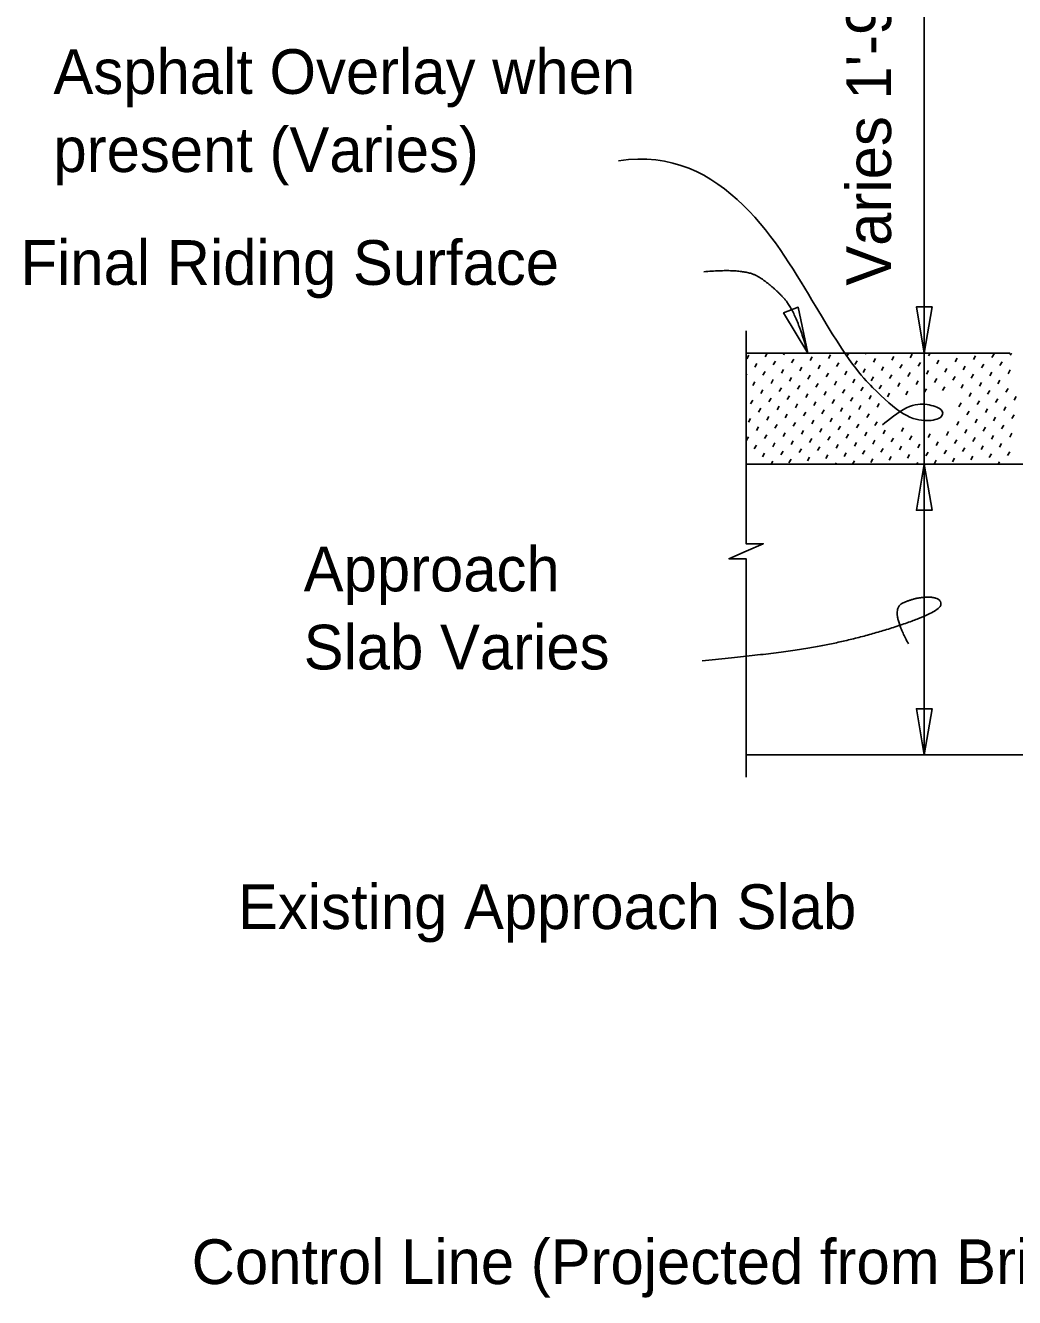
# Model space of a CAD drawing. Extents: x 21652.5 to 21723.2, y 56079.2 to 56117.9.
# Drawn here: x 21676.35 to 21680.81, y 56098.69 to 56104.42 of the extents above; entities that cross this region are included whole.
import ezdxf

# ---------------------------------------------------------------- set-up
doc = ezdxf.new("R2010")
doc.units = 0
for name, color, linetype in [('Dimension', 7, 'Continuous'), ('ExistSuperStruct', 7, 'Continuous'), ('Miscellaneous', 7, 'Continuous'), ('TextStructures', 7, 'Continuous')]:
    doc.layers.add(name, color=color, linetype=linetype)

msp = doc.modelspace()

# ---------------------------------------------------------------- linework, layer by layer
at = {"layer": 'Dimension'}
msp.add_line((21680.4032, 56108.278), (21680.4032, 56101.1329), dxfattribs=at)
for points in [[(21679.8776, 56102.9445), (21679.8349, 56103.1514), (21679.7692, 56103.1258)], [(21680.4032, 56102.9447), (21680.4385, 56103.1529), (21680.3679, 56103.1529)], [(21680.4032, 56102.4447), (21680.4385, 56102.2364), (21680.3679, 56102.2364)], [(21680.4032, 56101.1329), (21680.4385, 56101.3412), (21680.3679, 56101.3412)]]:
    msp.add_lwpolyline(points, close=True, dxfattribs=at)
msp.add_lwpolyline([(21679.5999, 56103.0446), (21679.5999, 56102.0849), (21679.6774, 56102.0849), (21679.5999, 56102.0511), (21679.5224, 56102.0174), (21679.5999, 56102.0174), (21679.5999, 56101.0329)], dxfattribs=at)
for points, degree in [([(21679.0254, 56103.8118), (21679.4979, 56103.8867), (21680.0133, 56102.9542), (21680.1732, 56102.7831), (21680.3149, 56102.6526), (21680.4198, 56102.6342), (21680.4892, 56102.6527), (21680.4892, 56102.6938), (21680.4184, 56102.7165), (21680.3319, 56102.7165), (21680.2412, 56102.6427), (21680.2143, 56102.6214)], 3), ([(21679.4099, 56103.3113), (21679.5913, 56103.3283), (21679.716, 56103.2517), (21679.8266, 56103.1297), (21679.8776, 56102.9445)], 2), ([(21679.402, 56101.5578), (21679.7617, 56101.5913), (21680.1276, 56101.6615), (21680.4782, 56101.7804), (21680.4782, 56101.8444), (21680.3624, 56101.8444), (21680.2465, 56101.7895), (21680.3319, 56101.634)], 2)]:
    msp.add_open_spline(points, degree=degree, dxfattribs=at)
at = {"layer": 'ExistSuperStruct'}
for p, q in [((21683.8894, 56102.4446), (21679.5999, 56102.4446)), ((21679.5999, 56101.1329), (21685.053, 56101.1329))]:
    msp.add_line(p, q, dxfattribs=at)
at = {"layer": 'Miscellaneous'}
for p, q in [((21680.789, 56102.9446), (21679.5999, 56102.9446)), ((21679.6027, 56102.9182), (21679.6124, 56102.935)), ((21679.6856, 56102.9279), (21679.6953, 56102.9446)), ((21679.7686, 56102.9376), (21679.7726, 56102.9446)), ((21679.8052, 56102.901), (21679.8149, 56102.9178)), ((21679.8881, 56102.9107), (21679.8978, 56102.9275)), ((21679.9711, 56102.9204), (21679.9808, 56102.9372)), ((21680.054, 56102.9302), (21680.0624, 56102.9446)), ((21680.0906, 56102.8936), (21680.1003, 56102.9104)), ((21680.1369, 56102.9399), (21680.1397, 56102.9446)), ((21680.1735, 56102.9033), (21680.1833, 56102.9201)), ((21680.2565, 56102.913), (21680.2662, 56102.9298)), ((21680.3394, 56102.9227), (21680.3491, 56102.9395)), ((21680.4224, 56102.9324), (21680.4294, 56102.9446)), ((21680.459, 56102.8958), (21680.4687, 56102.9126)), ((21680.5053, 56102.9422), (21680.5067, 56102.9446)), ((21680.5419, 56102.9056), (21680.5516, 56102.9224)), ((21680.6248, 56102.9153), (21680.6346, 56102.9321)), ((21680.7078, 56102.925), (21680.7175, 56102.9418)), ((21680.7907, 56102.9347), (21680.7964, 56102.9446)), ((21679.5999, 56102.8472), (21679.6027, 56102.852)), ((21679.6393, 56102.8816), (21679.649, 56102.8983)), ((21679.6759, 56102.8449), (21679.6856, 56102.8617)), ((21679.7222, 56102.8913), (21679.732, 56102.9081)), ((21679.7589, 56102.8547), (21679.7686, 56102.8715)), ((21679.8418, 56102.8644), (21679.8515, 56102.8812)), ((21679.9247, 56102.8741), (21679.9344, 56102.8909)), ((21679.9613, 56102.8375), (21679.9711, 56102.8543)), ((21680.0077, 56102.8838), (21680.0174, 56102.9006)), ((21680.0443, 56102.8472), (21680.054, 56102.864)), ((21680.1272, 56102.8569), (21680.1369, 56102.8737)), ((21680.2101, 56102.8667), (21680.2199, 56102.8835)), ((21680.2931, 56102.8764), (21680.3028, 56102.8932)), ((21680.3297, 56102.8398), (21680.3394, 56102.8566)), ((21680.376, 56102.8861), (21680.3857, 56102.9029)), ((21680.4126, 56102.8495), (21680.4224, 56102.8663)), ((21680.4956, 56102.8592), (21680.5053, 56102.876)), ((21680.5785, 56102.869), (21680.5882, 56102.8857)), ((21680.6614, 56102.8787), (21680.6712, 56102.8955)), ((21680.6981, 56102.8421), (21680.7078, 56102.8589)), ((21680.7444, 56102.8884), (21680.7541, 56102.9052)), ((21680.781, 56102.8518), (21680.7907, 56102.8686)), ((21679.6296, 56102.7986), (21679.6393, 56102.8154)), ((21679.7125, 56102.8083), (21679.7222, 56102.8251)), ((21679.7955, 56102.8181), (21679.8052, 56102.8349)), ((21679.8321, 56102.7815), (21679.8418, 56102.7982)), ((21679.8784, 56102.8278), (21679.8881, 56102.8446)), ((21679.915, 56102.7912), (21679.9247, 56102.808)), ((21679.9979, 56102.8009), (21680.0077, 56102.8177)), ((21680.0809, 56102.8106), (21680.0906, 56102.8274)), ((21680.1638, 56102.8203), (21680.1735, 56102.8371)), ((21680.2004, 56102.7837), (21680.2101, 56102.8005)), ((21680.2468, 56102.8301), (21680.2565, 56102.8469)), ((21680.2834, 56102.7935), (21680.2931, 56102.8103)), ((21680.3663, 56102.8032), (21680.376, 56102.82)), ((21680.4492, 56102.8129), (21680.459, 56102.8297)), ((21680.5322, 56102.8226), (21680.5419, 56102.8394)), ((21680.5688, 56102.786), (21680.5785, 56102.8028)), ((21680.6151, 56102.8323), (21680.6248, 56102.8491)), ((21680.6517, 56102.7957), (21680.6614, 56102.8125)), ((21680.7347, 56102.8055), (21680.7444, 56102.8223)), ((21679.6662, 56102.762), (21679.6759, 56102.7788)), ((21679.7028, 56102.7254), (21679.7125, 56102.7422)), ((21679.7491, 56102.7717), (21679.7589, 56102.7885)), ((21679.7857, 56102.7351), (21679.7955, 56102.7519)), ((21679.8687, 56102.7448), (21679.8784, 56102.7616)), ((21679.9516, 56102.7546), (21679.9613, 56102.7714)), ((21680.0345, 56102.7643), (21680.0443, 56102.7811)), ((21680.0712, 56102.7277), (21680.0809, 56102.7445)), ((21680.1175, 56102.774), (21680.1272, 56102.7908)), ((21680.1541, 56102.7374), (21680.1638, 56102.7542)), ((21680.237, 56102.7471), (21680.2468, 56102.7639)), ((21680.32, 56102.7568), (21680.3297, 56102.7736)), ((21680.4029, 56102.7666), (21680.4126, 56102.7834)), ((21680.4858, 56102.7763), (21680.4956, 56102.7931)), ((21680.6054, 56102.7494), (21680.6151, 56102.7662)), ((21680.6883, 56102.7591), (21680.6981, 56102.7759)), ((21680.7249, 56102.7225), (21680.7347, 56102.7393)), ((21680.7713, 56102.7689), (21680.781, 56102.7856)), ((21680.8079, 56102.7322), (21680.8176, 56102.749)), ((21679.6199, 56102.7157), (21679.6296, 56102.7325)), ((21679.6565, 56102.6791), (21679.6662, 56102.6959)), ((21679.7394, 56102.6888), (21679.7491, 56102.7056)), ((21679.8223, 56102.6985), (21679.8321, 56102.7153)), ((21679.9053, 56102.7082), (21679.915, 56102.725)), ((21679.9419, 56102.6716), (21679.9516, 56102.6884)), ((21679.9882, 56102.718), (21679.9979, 56102.7348)), ((21680.0248, 56102.6814), (21680.0345, 56102.6981)), ((21680.1078, 56102.6911), (21680.1175, 56102.7079)), ((21680.1907, 56102.7008), (21680.2004, 56102.7176)), ((21680.5591, 56102.7031), (21680.5688, 56102.7199)), ((21680.5957, 56102.6665), (21680.6054, 56102.6833)), ((21680.642, 56102.7128), (21680.6517, 56102.7296)), ((21680.6786, 56102.6762), (21680.6883, 56102.693)), ((21680.7615, 56102.6859), (21680.7713, 56102.7027)), ((21679.6101, 56102.6327), (21679.6199, 56102.6495)), ((21679.6931, 56102.6425), (21679.7028, 56102.6593)), ((21679.7297, 56102.6059), (21679.7394, 56102.6226)), ((21679.776, 56102.6522), (21679.7857, 56102.669)), ((21679.8126, 56102.6156), (21679.8223, 56102.6324)), ((21679.859, 56102.6619), (21679.8687, 56102.6787)), ((21679.8956, 56102.6253), (21679.9053, 56102.6421)), ((21679.9785, 56102.635), (21679.9882, 56102.6518)), ((21680.0614, 56102.6447), (21680.0712, 56102.6615)), ((21680.098, 56102.6081), (21680.1078, 56102.6249)), ((21680.1444, 56102.6545), (21680.1541, 56102.6713)), ((21680.181, 56102.6179), (21680.1907, 56102.6347)), ((21680.5493, 56102.6201), (21680.5591, 56102.6369)), ((21680.6323, 56102.6299), (21680.642, 56102.6467)), ((21680.7152, 56102.6396), (21680.7249, 56102.6564)), ((21680.7982, 56102.6493), (21680.8079, 56102.6661)), ((21679.6004, 56102.5498), (21679.6101, 56102.5666)), ((21679.6467, 56102.5961), (21679.6565, 56102.6129)), ((21679.6834, 56102.5595), (21679.6931, 56102.5763)), ((21679.7663, 56102.5692), (21679.776, 56102.586)), ((21679.8492, 56102.579), (21679.859, 56102.5958)), ((21679.9322, 56102.5887), (21679.9419, 56102.6055)), ((21679.9688, 56102.5521), (21679.9785, 56102.5689)), ((21680.0151, 56102.5984), (21680.0248, 56102.6152)), ((21680.0517, 56102.5618), (21680.0614, 56102.5786)), ((21680.1346, 56102.5715), (21680.1444, 56102.5883)), ((21680.2176, 56102.5813), (21680.2273, 56102.598)), ((21680.3005, 56102.591), (21680.3102, 56102.6078)), ((21680.3371, 56102.5544), (21680.3469, 56102.5712)), ((21680.4201, 56102.5641), (21680.4298, 56102.5809)), ((21680.503, 56102.5738), (21680.5127, 56102.5906)), ((21680.5859, 56102.5835), (21680.5957, 56102.6003)), ((21680.6689, 56102.5933), (21680.6786, 56102.6101)), ((21680.7055, 56102.5566), (21680.7152, 56102.5734)), ((21680.7518, 56102.603), (21680.7615, 56102.6198)), ((21680.7884, 56102.5664), (21680.7982, 56102.5832)), ((21679.637, 56102.5132), (21679.6467, 56102.53)), ((21679.72, 56102.5229), (21679.7297, 56102.5397)), ((21679.8029, 56102.5326), (21679.8126, 56102.5494)), ((21679.8395, 56102.496), (21679.8492, 56102.5128)), ((21679.8858, 56102.5424), (21679.8956, 56102.5592)), ((21679.9224, 56102.5058), (21679.9322, 56102.5225)), ((21680.0054, 56102.5155), (21680.0151, 56102.5323)), ((21680.0883, 56102.5252), (21680.098, 56102.542)), ((21680.1713, 56102.5349), (21680.181, 56102.5517)), ((21680.2079, 56102.4983), (21680.2176, 56102.5151)), ((21680.2542, 56102.5446), (21680.2639, 56102.5614)), ((21680.2908, 56102.508), (21680.3005, 56102.5248)), ((21680.3737, 56102.5178), (21680.3835, 56102.5346)), ((21680.4567, 56102.5275), (21680.4664, 56102.5443)), ((21680.4933, 56102.4909), (21680.503, 56102.5077)), ((21680.5396, 56102.5372), (21680.5493, 56102.554)), ((21680.5762, 56102.5006), (21680.5859, 56102.5174)), ((21680.6226, 56102.5469), (21680.6323, 56102.5637)), ((21680.6592, 56102.5103), (21680.6689, 56102.5271)), ((21680.7421, 56102.52), (21680.7518, 56102.5368)), ((21679.5999, 56102.4828), (21679.6004, 56102.4837)), ((21679.6736, 56102.4766), (21679.6834, 56102.4934)), ((21679.7129, 56102.4446), (21679.72, 56102.4568)), ((21679.7566, 56102.4863), (21679.7663, 56102.5031)), ((21679.7932, 56102.4497), (21679.8029, 56102.4665)), ((21679.8761, 56102.4594), (21679.8858, 56102.4762)), ((21679.9591, 56102.4691), (21679.9688, 56102.4859)), ((21680.042, 56102.4789), (21680.0517, 56102.4957)), ((21680.08, 56102.4446), (21680.0883, 56102.4591)), ((21680.1249, 56102.4886), (21680.1346, 56102.5054)), ((21680.1615, 56102.452), (21680.1713, 56102.4688)), ((21680.2445, 56102.4617), (21680.2542, 56102.4785)), ((21680.3274, 56102.4714), (21680.3371, 56102.4882)), ((21680.3697, 56102.4446), (21680.3737, 56102.4516)), ((21680.4103, 56102.4812), (21680.4201, 56102.4979)), ((21680.447, 56102.4446), (21680.4567, 56102.4613)), ((21680.5299, 56102.4543), (21680.5396, 56102.4711)), ((21680.6128, 56102.464), (21680.6226, 56102.4808)), ((21680.6958, 56102.4737), (21680.7055, 56102.4905)), ((21680.7367, 56102.4446), (21680.7421, 56102.4539)), ((21680.7787, 56102.4834), (21680.7884, 56102.5002)), ((21679.6356, 56102.4446), (21679.637, 56102.447)), ((21680.0027, 56102.4446), (21680.0054, 56102.4493))]:
    msp.add_line(p, q, dxfattribs=at)

# ---------------------------------------------------------------- texts
at = {"layer": 'Dimension'}
for s, p in [('Asphalt Overlay when ', (21676.4775, 56104.1132)), ('present (Varies)', (21676.4775, 56103.7612)), ('Approach', (21677.6056, 56101.8706)), ('Slab Varies', (21677.6056, 56101.5186))]:
    msp.add_text(s, height=0.2016, dxfattribs=at).set_placement(p)
at = {"layer": 'TextStructures'}
msp.add_text('Varies 1\'-9" to 2\'-0"', height=0.2016, rotation=90, dxfattribs=at).set_placement((21680.2533, 56103.2486))
for s, p in [('Final Riding Surface', (21676.3291, 56103.2523)), ('Existing Approach Slab', (21677.3093, 56100.3482)), ('Control Line (Projected from Bridge)', (21677.1007, 56098.7476))]:
    msp.add_text(s, height=0.2016, dxfattribs=at).set_placement(p)

doc.saveas('drawing.dxf')
